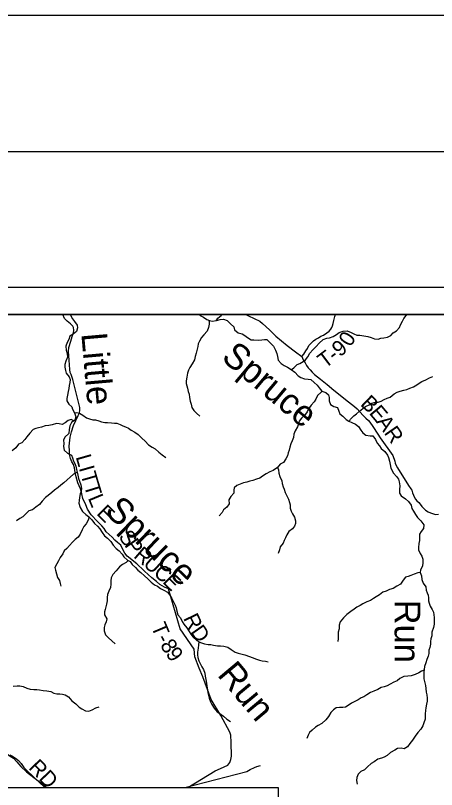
# Model space of a CAD drawing. Extents: x 0 to 34, y 0 to 22.
# Drawn here: x 3.475 to 5.025, y 19.152 to 22 of the extents above; entities that cross this region are included whole.
import ezdxf

# ---------------------------------------------------------------- set-up
doc = ezdxf.new("R2010")
doc.units = 0
for name, color, linetype in [('Default', 7, 'Continuous'), ('GM_X_County_Road', 7, 'Continuous'), ('GM_X_County_Road_Text', 7, 'Continuous'), ('GM_X_Minor_River', 7, 'Continuous'), ('GM_X_Minor_River_Text', 7, 'Continuous'), ('GM_X_Township_Road', 7, 'Continuous'), ('GM_X_Township_Road_Text', 7, 'Continuous'), ('SH_Border', 7, 'Continuous'), ('SH_Cut_Line', 7, 'Continuous'), ('SH_Data', 7, 'Continuous'), ('SH_Text', 7, 'Continuous')]:
    doc.layers.add(name, color=color, linetype=linetype)

msp = doc.modelspace()

# ---------------------------------------------------------------- linework, layer by layer
at = {"layer": 'Default'}
msp.add_lwpolyline([(6.416, 20.9), (2.4845, 20.9)], dxfattribs=at)
at = {"layer": 'GM_X_County_Road'}
msp.add_lwpolyline([(4.3231, 20.9), (4.3324, 20.8951), (4.3741, 20.8748), (4.3839, 20.867), (4.4096, 20.8432), (4.4335, 20.8197), (4.4747, 20.7858), (4.5065, 20.7623), (4.5286, 20.7453), (4.5344, 20.7334), (4.5416, 20.7214), (4.5469, 20.712), (4.5525, 20.7041), (4.5594, 20.6957), (4.567, 20.6873), (4.5759, 20.6795), (4.598, 20.6614), (4.6224, 20.6418), (4.6469, 20.6212), (4.7007, 20.5781), (4.7232, 20.5614), (4.7333, 20.5528), (4.7539, 20.5294), (4.7644, 20.5187), (4.774, 20.5093), (4.7794, 20.5037), (4.7906, 20.4872), (4.8089, 20.4592), (4.8178, 20.4457), (4.8635, 20.3806), (4.8671, 20.3738), (4.8691, 20.3679), (4.8714, 20.36), (4.873, 20.3524), (4.8765, 20.344), (4.8813, 20.3354), (4.9223, 20.2713), (4.9304, 20.2588), (4.9337, 20.253), (4.937, 20.2435), (4.9398, 20.2354), (4.9424, 20.2285), (4.9475, 20.2209), (4.9523, 20.2145), (4.9592, 20.2079), (4.9648, 20.2016), (4.9709, 20.1934), (4.9782, 20.1856), (4.9843, 20.1802), (4.9938, 20.1741), (5.0032, 20.1698), (5.0133, 20.1662), (5.0212, 20.1644), (5.0322, 20.165)], dxfattribs=at)
at = {"layer": 'GM_X_Minor_River'}
for points in [[(3.6775, 20.9), (3.6777, 20.8975), (3.6856, 20.8841), (3.6924, 20.8742), (3.7021, 20.8609), (3.7032, 20.851), (3.7005, 20.8377), (3.6879, 20.8279), (3.6757, 20.8204), (3.6718, 20.8075), (3.6653, 20.7965), (3.6603, 20.7833), (3.6617, 20.7692), (3.6658, 20.7559), (3.6665, 20.7426), (3.6603, 20.7282), (3.6564, 20.7153), (3.6575, 20.7058), (3.6589, 20.6936), (3.6623, 20.6837), (3.6724, 20.6711), (3.6765, 20.6601), (3.6757, 20.6499), (3.6733, 20.6392), (3.6717, 20.6271), (3.6694, 20.6168), (3.6667, 20.6032), (3.6643, 20.5914), (3.6646, 20.5816), (3.6721, 20.5705), (3.6823, 20.5605), (3.6856, 20.551), (3.692, 20.5381), (3.6972, 20.5232), (3.6937, 20.5107), (3.6811, 20.5021), (3.6754, 20.4903), (3.6734, 20.4767), (3.6714, 20.4626), (3.6565, 20.449), (3.6515, 20.4373), (3.6537, 20.4251), (3.6525, 20.4137), (3.6551, 20.4012), (3.6671, 20.3893), (3.6815, 20.3828), (3.6852, 20.3729), (3.6885, 20.3607), (3.6934, 20.3512), (3.6975, 20.3417), (3.6997, 20.3295), (3.7027, 20.3196), (3.7053, 20.3089), (3.7075, 20.2968), (3.7112, 20.2869), (3.716, 20.2728), (3.7182, 20.2595), (3.7166, 20.25), (3.7131, 20.2401), (3.7104, 20.2261), (3.7092, 20.2155), (3.7091, 20.206), (3.7132, 20.1892), (3.7214, 20.1748), (3.7342, 20.1637), (3.7441, 20.1571), (3.7565, 20.1441), (3.7666, 20.1312), (3.7776, 20.1212), (3.7855, 20.1113), (3.7941, 20.0979), (3.8035, 20.085), (3.8141, 20.0769), (3.8265, 20.0643), (3.8344, 20.0517), (3.846, 20.0395)], [(4.1871, 20.8783), (4.188, 20.8737), (4.1883, 20.8642), (4.1859, 20.8521), (4.1805, 20.8388), (4.1691, 20.8256), (4.1595, 20.8154), (4.1522, 20.8021), (4.148, 20.7919), (4.146, 20.7817), (4.1429, 20.7673), (4.1402, 20.7574), (4.1371, 20.7453), (4.1336, 20.7331), (4.1251, 20.718), (4.1167, 20.7044), (4.1121, 20.6945), (4.1086, 20.6843), (4.1055, 20.6695), (4.1038, 20.6562), (4.1038, 20.6463), (4.1086, 20.6285), (4.1112, 20.6167), (4.1141, 20.6064), (4.1156, 20.595), (4.1185, 20.5809), (4.1222, 20.5703), (4.1248, 20.5573), (4.1319, 20.5466), (4.141, 20.5371), (4.1534, 20.5264)], [(4.1514, 20.9), (4.1548, 20.8959), (4.1676, 20.8902)], [(4.1676, 20.8902), (4.1793, 20.881), (4.1895, 20.8775), (4.1997, 20.8748), (4.2149, 20.8773), (4.2282, 20.8818), (4.2415, 20.8825), (4.2547, 20.8775), (4.2672, 20.8652), (4.2785, 20.8549), (4.2814, 20.8439), (4.2954, 20.8328), (4.3094, 20.8281), (4.3192, 20.822), (4.3294, 20.8154), (4.3426, 20.807), (4.3529, 20.8062), (4.3684, 20.8057), (4.3817, 20.8071), (4.3912, 20.8082), (4.4006, 20.8074), (4.4131, 20.7955), (4.4244, 20.7837), (4.4322, 20.7692), (4.4367, 20.7559), (4.4393, 20.7448), (4.4418, 20.7323), (4.4535, 20.7201), (4.4641, 20.7128), (4.4766, 20.7062), (4.4898, 20.6978), (4.503, 20.6875), (4.5154, 20.6737), (4.5252, 20.6683), (4.5392, 20.6633), (4.5525, 20.6621), (4.562, 20.6613), (4.5752, 20.6502), (4.5857, 20.6395), (4.5936, 20.6299), (4.6034, 20.6177), (4.6174, 20.6127), (4.6279, 20.6046), (4.6294, 20.5947), (4.6293, 20.5826), (4.6353, 20.5689), (4.647, 20.5616), (4.6606, 20.5581), (4.6654, 20.544), (4.6692, 20.5345), (4.6797, 20.5253), (4.6922, 20.5138), (4.7024, 20.508), (4.713, 20.5027), (4.7266, 20.4965), (4.7375, 20.4877), (4.7469, 20.4739), (4.7533, 20.4644), (4.7646, 20.4556), (4.7801, 20.4536), (4.7911, 20.4535), (4.8009, 20.4398), (4.8069, 20.4268), (4.8148, 20.4162), (4.8211, 20.4066), (4.8343, 20.3955), (4.8445, 20.3829), (4.8478, 20.3734), (4.8523, 20.3608), (4.8537, 20.3483), (4.8571, 20.335), (4.8668, 20.3159), (4.8777, 20.3041), (4.8849, 20.2942), (4.8878, 20.2843), (4.8896, 20.2691), (4.8888, 20.2554), (4.8883, 20.2429), (4.8947, 20.2326), (4.9109, 20.2222), (4.9222, 20.2115), (4.9312, 20.1985), (4.9342, 20.1856), (4.9398, 20.1757), (4.9473, 20.1635), (4.9552, 20.1528), (4.9673, 20.1413), (4.9781, 20.1257), (4.9773, 20.1128), (4.9689, 20.1018), (4.962, 20.092), (4.9627, 20.0787), (4.9626, 20.0688), (4.9599, 20.057), (4.959, 20.043), (4.9589, 20.0335), (4.9649, 20.0205), (4.9709, 20.0102), (4.9739, 20), (4.9746, 19.987), (4.9737, 19.9738)], [(4.2135, 20.8771), (4.2199, 20.8868), (4.2329, 20.8962), (4.236, 20.9)], [(4.4909, 20.6969), (4.4997, 20.7034), (4.5119, 20.7155), (4.5222, 20.72), (4.5336, 20.7268), (4.5431, 20.7332), (4.5511, 20.7441), (4.5592, 20.7581), (4.5691, 20.7695), (4.5821, 20.7823), (4.5928, 20.7944), (4.6073, 20.8083), (4.6206, 20.8132), (4.6316, 20.8135), (4.6445, 20.8191), (4.6571, 20.8259), (4.6666, 20.8338), (4.6811, 20.8383), (4.6955, 20.8401), (4.7102, 20.8331), (4.7205, 20.8293), (4.7322, 20.8239), (4.7424, 20.8238), (4.7572, 20.8211), (4.7723, 20.8191), (4.7844, 20.8152), (4.7965, 20.8109), (4.8102, 20.8093), (4.8201, 20.813), (4.8307, 20.8141), (4.844, 20.8163), (4.8569, 20.8227), (4.8653, 20.8325), (4.8771, 20.8393), (4.8886, 20.8514), (4.8928, 20.862), (4.8994, 20.8752), (4.9051, 20.8851), (4.9128, 20.8956), (4.9151, 20.9)], [(4.7042, 20.5071), (4.7077, 20.5145), (4.7207, 20.5269), (4.7302, 20.5348), (4.7409, 20.5443), (4.7531, 20.5544), (4.7638, 20.5616), (4.7771, 20.568), (4.7874, 20.574), (4.8007, 20.5777), (4.8101, 20.5772), (4.8208, 20.581), (4.8326, 20.5877), (4.8429, 20.5922), (4.8546, 20.5963), (4.8695, 20.6076), (4.8805, 20.6136), (4.8916, 20.6174), (4.9049, 20.6214), (4.9159, 20.6244), (4.9269, 20.6285), (4.9398, 20.6341), (4.952, 20.6413), (4.9615, 20.6477), (4.9711, 20.6537), (4.9855, 20.6597), (4.9996, 20.6664), (5.011, 20.6713)], [(4.6041, 20.6174), (4.5995, 20.6124), (4.5873, 20.6015), (4.5804, 20.5882), (4.5747, 20.578), (4.5636, 20.5663), (4.5536, 20.5531), (4.5494, 20.5413), (4.5395, 20.5285), (4.5284, 20.5183), (4.5196, 20.5073), (4.5165, 20.4978), (4.5134, 20.4868), (4.5042, 20.4721), (4.4996, 20.4596), (4.498, 20.4478), (4.4933, 20.4349), (4.4883, 20.4243), (4.4848, 20.4118), (4.4829, 20.4012), (4.4786, 20.3906), (4.4759, 20.3803), (4.4705, 20.3682), (4.4621, 20.3557), (4.4499, 20.3494), (4.4392, 20.3369), (4.4243, 20.326), (4.4118, 20.3215), (4.3985, 20.314), (4.3844, 20.3046), (4.3741, 20.2971), (4.3619, 20.2941), (4.3483, 20.2892), (4.3384, 20.2863), (4.3274, 20.2833), (4.3144, 20.28), (4.3019, 20.2755), (4.2905, 20.2702), (4.2802, 20.2627), (4.2794, 20.2532), (4.2785, 20.2426), (4.2678, 20.2305), (4.2609, 20.2184), (4.2612, 20.2036), (4.2536, 20.1907), (4.2406, 20.1813), (4.2356, 20.1715), (4.2249, 20.1594)], [(3.6921, 20.5379), (3.7, 20.5388), (3.7106, 20.5368), (3.7238, 20.5291), (3.737, 20.5196), (3.748, 20.5164), (3.7605, 20.5126), (3.7703, 20.5117), (3.7817, 20.5083), (3.7915, 20.5055), (3.8044, 20.5028), (3.8146, 20.5027), (3.8286, 20.5007), (3.8393, 20.4999), (3.8487, 20.4995), (3.8605, 20.4956), (3.8703, 20.4906), (3.8805, 20.4871), (3.8907, 20.4821), (3.9017, 20.4748), (3.9141, 20.4675), (3.927, 20.4579), (3.9398, 20.4453), (3.953, 20.4338), (3.965, 20.4201), (3.979, 20.4113), (3.9892, 20.4055), (4.0027, 20.3929), (4.0152, 20.3841), (4.0288, 20.3737)], [(3.6901, 20.5082), (3.6805, 20.5131), (3.6687, 20.5101), (3.6588, 20.5018), (3.647, 20.4954), (3.6367, 20.497), (3.6258, 20.4982), (3.6098, 20.4942), (3.5977, 20.492), (3.584, 20.4898), (3.5711, 20.4857), (3.5601, 20.4823), (3.5502, 20.4809), (3.5399, 20.4764), (3.5285, 20.4635), (3.5166, 20.4503), (3.5097, 20.4401), (3.499, 20.428), (3.4868, 20.4224), (3.4765, 20.4092), (3.4634, 20.3985)], [(4.4395, 20.3373), (4.4429, 20.3278), (4.4447, 20.316), (4.4485, 20.3042), (4.4552, 20.2878), (4.4574, 20.2783), (4.4611, 20.2661), (4.4637, 20.2566), (4.4682, 20.2444), (4.4749, 20.2303), (4.4801, 20.22), (4.4842, 20.2086), (4.4864, 20.1991), (4.4867, 20.1873), (4.4901, 20.1767), (4.4946, 20.1664), (4.5024, 20.1538), (4.5061, 20.1409), (4.5053, 20.1314), (4.5018, 20.1215), (4.4949, 20.1109), (4.4812, 20.1019), (4.4739, 20.0894), (4.4697, 20.0776), (4.4643, 20.0678), (4.4608, 20.058), (4.4494, 20.0447), (4.4474, 20.0341), (4.4416, 20.0209)], [(3.7024, 20.3205), (3.6985, 20.317), (3.689, 20.3128), (3.6772, 20.3015), (3.6653, 20.291), (3.6527, 20.28), (3.6421, 20.2721), (3.6322, 20.2635), (3.6192, 20.2533), (3.6097, 20.2454), (3.5959, 20.2337), (3.5864, 20.2269), (3.5738, 20.2133), (3.5639, 20.2008), (3.5505, 20.1907), (3.5379, 20.1816), (3.5246, 20.1772), (3.512, 20.1647), (3.5021, 20.156), (3.4918, 20.1489), (3.4785, 20.1402)], [(3.7461, 20.155), (3.7432, 20.1427), (3.7352, 20.1298), (3.7275, 20.12), (3.7206, 20.1071), (3.7133, 20.092), (3.7064, 20.0806), (3.6953, 20.072), (3.685, 20.0618), (3.674, 20.0497), (3.6644, 20.0391), (3.6549, 20.0305), (3.6491, 20.0195), (3.6395, 20.0059), (3.6338, 19.993), (3.628, 19.9831), (3.6203, 19.9695), (3.6222, 19.9596), (3.6303, 19.9322), (3.6378, 19.9208), (3.64, 19.9101), (3.6419, 19.9006)], [(3.846, 20.0395), (3.857, 20.0299), (3.8679, 20.0185), (3.8743, 20.0078), (3.8875, 19.9963), (3.8973, 19.9913), (3.9044, 19.9802), (3.9165, 19.9695), (3.9259, 19.9588), (3.9368, 19.95), (3.9504, 19.9382), (3.9621, 19.9278), (3.9753, 19.9148), (3.9873, 19.9056), (3.9976, 19.9003), (4.0092, 19.8914), (4.0217, 19.8853), (4.0346, 19.878), (4.0432, 19.8669), (4.0503, 19.8547), (4.0578, 19.8402), (4.0634, 19.8307), (4.0668, 19.8204), (4.069, 19.8079), (4.0727, 19.7953), (4.0821, 19.7842), (4.0885, 19.7709), (4.0944, 19.7606), (4.1065, 19.7476), (4.1144, 19.7331), (4.1207, 19.7232), (4.1298, 19.7129), (4.1433, 19.7003), (4.1562, 19.693), (4.1713, 19.6876), (4.185, 19.6863), (4.1944, 19.6855), (4.2047, 19.6832), (4.2187, 19.6812), (4.2301, 19.6811), (4.2426, 19.6795), (4.2566, 19.6756), (4.269, 19.6679), (4.2834, 19.658), (4.2951, 19.6537), (4.3053, 19.6514), (4.3193, 19.6475), (4.3367, 19.6413), (4.3466, 19.6374), (4.3624, 19.6313), (4.373, 19.6281), (4.3829, 19.6254), (4.3958, 19.6238), (4.4056, 19.6222)], [(3.89, 19.995), (3.8825, 19.9876), (3.8695, 19.9805), (3.8577, 19.971), (3.8462, 19.9567), (3.8336, 19.9435), (3.8271, 19.9314), (3.8263, 19.9203), (3.8262, 19.9082), (3.8246, 19.8953), (3.8188, 19.8824), (3.8138, 19.8695), (3.8126, 19.8585), (3.8133, 19.8467), (3.8098, 19.8338), (3.8078, 19.8244), (3.8059, 19.8149), (3.8035, 19.8054), (3.8031, 19.7944), (3.8117, 19.7799), (3.8097, 19.7696), (3.8047, 19.7583), (3.802, 19.748), (3.8012, 19.7359), (3.8068, 19.7218), (3.8173, 19.71), (3.8305, 19.6996), (3.8426, 19.6882)], [(4.9737, 19.9738), (4.966, 19.9609), (4.9652, 19.951), (4.9693, 19.9381), (4.9707, 19.9252), (4.9756, 19.9111), (4.985, 19.8981), (4.9864, 19.8859), (4.9901, 19.8764), (4.9946, 19.8669), (4.9957, 19.857), (4.9956, 19.8467), (4.9975, 19.8372), (5.0016, 19.8262), (5.0083, 19.8144), (5.0139, 19.8045), (5.0154, 19.795), (5.0164, 19.7847), (5.0163, 19.7604), (5.0143, 19.7486), (5.0081, 19.7316), (5.0073, 19.7179), (5.0038, 19.7069), (5.003, 19.6967), (5.0029, 19.6868), (4.9998, 19.6746), (4.9967, 19.6652), (4.9966, 19.6526), (4.9943, 19.6428), (4.9889, 19.6303), (4.9854, 19.6178), (4.9804, 19.6053), (4.9791, 19.5943), (4.9783, 19.5836), (4.9779, 19.5738), (4.9782, 19.5597), (4.9807, 19.5494), (4.9848, 19.535), (4.9851, 19.5239), (4.9862, 19.5103), (4.9888, 19.5007), (4.9909, 19.4878), (4.9909, 19.4768), (4.9885, 19.4666), (4.985, 19.4525), (4.9838, 19.4427), (4.983, 19.4301), (4.9837, 19.4206), (4.9836, 19.4108), (4.9786, 19.3971), (4.974, 19.3865), (4.9674, 19.3736), (4.9564, 19.3616), (4.946, 19.3483), (4.9361, 19.3343), (4.9265, 19.3211), (4.9185, 19.3086), (4.9055, 19.3022), (4.8945, 19.3046), (4.8813, 19.3032), (4.8714, 19.2975), (4.8561, 19.2881), (4.8432, 19.2776), (4.8325, 19.2708), (4.8223, 19.2678), (4.8093, 19.2634), (4.7956, 19.2539), (4.7838, 19.2476), (4.7712, 19.2355), (4.7594, 19.2249), (4.7465, 19.2182), (4.7369, 19.2091), (4.7319, 19.1962), (4.7307, 19.1856), (4.7329, 19.1719)], [(4.9652, 19.951), (4.9557, 19.9496), (4.9432, 19.9443), (4.9299, 19.9391), (4.9204, 19.9361), (4.9105, 19.9331), (4.9017, 19.9222), (4.8921, 19.9082), (4.8792, 19.8999), (4.8659, 19.892), (4.8518, 19.8876), (4.8396, 19.8816), (4.8278, 19.8778), (4.8149, 19.868), (4.8031, 19.8605), (4.7924, 19.8545), (4.7814, 19.847), (4.7681, 19.8429), (4.754, 19.835), (4.7437, 19.8294), (4.7312, 19.8234), (4.7213, 19.8162), (4.7091, 19.8076), (4.6946, 19.7966), (4.6831, 19.7842), (4.6705, 19.7694), (4.6663, 19.7569), (4.6662, 19.7436), (4.663, 19.7311), (4.6626, 19.7213), (4.6629, 19.7083), (4.6621, 19.6962)], [(4.1507, 19.6961), (4.1493, 19.6843), (4.1477, 19.6718), (4.1453, 19.6581), (4.1453, 19.6478), (4.1467, 19.6383), (4.1501, 19.6258), (4.156, 19.6132), (4.1609, 19.6033), (4.1669, 19.5934), (4.1725, 19.5797), (4.1739, 19.5687), (4.1754, 19.5565), (4.1783, 19.5432), (4.1798, 19.5333), (4.1816, 19.5192), (4.183, 19.5082), (4.1856, 19.4983), (4.1886, 19.4888), (4.193, 19.4743), (4.1979, 19.4648), (4.2065, 19.4514), (4.2178, 19.4385), (4.228, 19.4323), (4.2412, 19.4216), (4.2533, 19.4109), (4.2661, 19.4024)], [(4.9789, 19.5908), (4.9692, 19.5875), (4.9597, 19.5811), (4.9464, 19.5755), (4.932, 19.5702), (4.9187, 19.5696), (4.9043, 19.5678), (4.8898, 19.5606), (4.8799, 19.5523), (4.8673, 19.5475), (4.854, 19.54), (4.843, 19.5336), (4.8316, 19.5299), (4.8217, 19.5273), (4.8084, 19.5198), (4.7947, 19.5145), (4.7814, 19.5089), (4.7688, 19.5003), (4.7574, 19.4935), (4.7479, 19.489), (4.7365, 19.4826), (4.7247, 19.4762), (4.7117, 19.4699), (4.6999, 19.4616), (4.6896, 19.4552), (4.6798, 19.4534), (4.6673, 19.4534), (4.6555, 19.4527), (4.6456, 19.4452), (4.6357, 19.4358), (4.6269, 19.4214), (4.6177, 19.4085), (4.6028, 19.3946), (4.5891, 19.3878), (4.5796, 19.3818), (4.5674, 19.3701), (4.5578, 19.3618), (4.5528, 19.3516), (4.5471, 19.3399)], [(3.4672, 19.5318), (3.4813, 19.5336), (3.4908, 19.5335), (3.5033, 19.5308), (3.5173, 19.5254), (3.5297, 19.5215), (3.543, 19.5199), (3.554, 19.5198), (3.5635, 19.519), (3.5767, 19.5163), (3.5908, 19.5154), (3.6051, 19.5127), (3.6165, 19.5069), (3.6278, 19.5038), (3.6385, 19.5045), (3.6479, 19.5033), (3.6582, 19.5005), (3.6702, 19.4929), (3.6823, 19.4787), (3.697, 19.4676), (3.7098, 19.4546), (3.72, 19.4485), (3.7328, 19.4416), (3.7453, 19.44), (3.7579, 19.4456), (3.7705, 19.4531), (3.7834, 19.4568)], [(3.4542, 19.2796), (3.4621, 19.2766), (3.4753, 19.2677), (3.4859, 19.2593), (3.4964, 19.2475), (3.5062, 19.2337), (3.5186, 19.2207), (3.5835, 19.1594)], [(4.099, 19.1594), (4.3263, 19.2186), (4.3393, 19.2261), (4.3545, 19.2332), (4.364, 19.237), (4.3765, 19.2407)]]:
    msp.add_lwpolyline(points, dxfattribs=at)
at = {"layer": 'GM_X_Township_Road'}
for points in [[(3.9502, 19.9557), (3.9472, 19.9584), (3.9215, 19.9829), (3.8869, 20.0108), (3.8775, 20.0218), (3.8681, 20.0403), (3.8628, 20.0513), (3.8513, 20.0607), (3.8404, 20.0698), (3.8307, 20.0805), (3.8198, 20.0907), (3.8089, 20.1006), (3.8012, 20.1126), (3.7936, 20.1222), (3.7773, 20.1383), (3.7542, 20.1624), (3.7407, 20.1838), (3.7338, 20.1995), (3.7234, 20.2227), (3.7196, 20.2395), (3.7142, 20.2583), (3.705, 20.2809), (3.6987, 20.302), (3.6954, 20.3186), (3.6926, 20.3351), (3.6886, 20.3481), (3.6832, 20.3582), (3.6781, 20.3704), (3.6746, 20.3844), (3.6736, 20.4), (3.6728, 20.416), (3.6751, 20.4371), (3.6768, 20.4485), (3.6814, 20.4686), (3.6893, 20.492), (3.7066, 20.5284), (3.7104, 20.5382), (3.7127, 20.5477), (3.7125, 20.5571), (3.6868, 20.6606), (3.6799, 20.6789), (3.6769, 20.6868), (3.6748, 20.6973), (3.6728, 20.7321), (3.6705, 20.7639), (3.6723, 20.7786), (3.6789, 20.8013), (3.6837, 20.8191), (3.6883, 20.8328), (3.6901, 20.8427), (3.6893, 20.8516), (3.6865, 20.8573), (3.6784, 20.8649), (3.6659, 20.8748), (3.6552, 20.8852), (3.6491, 20.8994), (3.6491, 20.9)], [(4.5286, 20.7453), (4.5363, 20.7535), (4.5441, 20.7659), (4.5495, 20.7746), (4.5555, 20.7856), (4.564, 20.7949), (4.5724, 20.8024), (4.5813, 20.8087), (4.5902, 20.814), (4.5991, 20.8197), (4.6087, 20.8242), (4.6218, 20.8322), (4.63, 20.8387), (4.6356, 20.8455), (4.6391, 20.8518), (4.6423, 20.8582), (4.6448, 20.867), (4.6469, 20.8776), (4.6511, 20.8923), (4.6531, 20.9)], [(4.1518, 19.5989), (4.1356, 19.6407), (4.1333, 19.6681), (4.0814, 19.7434), (4.038, 19.8905), (4.0233, 19.8961), (4.0065, 19.9068), (3.9938, 19.917), (3.9772, 19.9307), (3.9502, 19.9557)], [(4.1092, 19.1594), (4.21, 19.2208), (4.2295, 19.2289), (4.2573, 19.242), (4.264, 19.2519), (4.2681, 19.2632), (4.2703, 19.2746), (4.2687, 19.3252), (4.2675, 19.3518), (4.2638, 19.3627), (4.2312, 19.4247), (4.1953, 19.4835), (4.1643, 19.5667), (4.1518, 19.5989)], [(3.108, 19.5852), (3.1171, 19.5808), (3.1313, 19.5736), (3.1822, 19.5459), (3.1977, 19.5378), (3.2094, 19.5302), (3.2239, 19.5185), (3.2376, 19.5035), (3.2529, 19.4834), (3.2763, 19.4498), (3.2941, 19.4277), (3.3246, 19.3933), (3.3684, 19.3473), (3.4093, 19.3132), (3.433, 19.2921), (3.4559, 19.2746), (3.4686, 19.2672), (3.4808, 19.2542), (3.495, 19.2374), (3.5161, 19.2168), (3.5906, 19.1594)]]:
    msp.add_lwpolyline(points, dxfattribs=at)
at = {"layer": 'SH_Border'}
msp.add_lwpolyline([(1.5, 21.5), (33.5, 21.5), (33.5, 0.5), (1.5, 0.5)], close=True, dxfattribs=at)
at = {"layer": 'SH_Cut_Line'}
for points in [[(0, 0), (34, 0), (34, 22), (0, 22)], [(2.4352, 14.1), (8.9, 14.1), (8.9, 20.9), (2.4845, 20.9), (2.4809, 20.6393), (2.4757, 20.2566), (2.4573, 18.9074), (2.4581, 18.1825), (2.4581, 18.1772), (2.4586, 17.7785), (2.4545, 17.2795), (2.4313, 15.0183), (2.4372, 14.2719)]]:
    msp.add_lwpolyline(points, close=True, dxfattribs=at)
at = {"layer": 'SH_Data'}
for p, q in [((2, 21), (9, 21)), ((2.1, 20.9), (8.9, 20.9))]:
    msp.add_line(p, q, dxfattribs=at)
at = {"layer": 'SH_Text'}
msp.add_lwpolyline([(2.9469, 19.1594), (4.4427, 19.1594), (4.4427, 18.673), (2.9469, 18.673)], close=True, dxfattribs=at)

# ---------------------------------------------------------------- texts
at = {"layer": 'GM_X_County_Road_Text'}
for s, rotation, p in [('B', 316.2586, (4.7417, 20.5678)), ('E', 310.0695, (4.7743, 20.5367)), ('A', 305.3907, (4.8009, 20.5051)), ('R', 304.8376, (4.8298, 20.4645))]:
    msp.add_text(s, height=0.0568, rotation=rotation, dxfattribs=at).set_placement(p)
at = {"layer": 'GM_X_Minor_River_Text'}
for s, rotation, p in [('Little', 275.0003, (3.7175, 20.8297)), ('Spruce', 319.9985, (4.2288, 20.7357)), ('Spruce', 315.9986, (3.7996, 20.1726)), ('Run', 270.0019, (4.8706, 19.8505)), ('Run', 309.9988, (4.2152, 19.5732))]:
    msp.add_text(s, height=0.0947, rotation=rotation, dxfattribs=at).set_placement(p)
at = {"layer": 'GM_X_Township_Road_Text'}
for s, height, rotation, p in [('0', 0.0568, 57.2884, (4.7081, 20.7778)), ('9', 0.0568, 40.6727, (4.6698, 20.7415)), ('T', 0.0568, 37.1296, (4.6145, 20.6991)), ('-', 0.0568, 37.7691, (4.6489, 20.7252)), ('L', 0.0568, 285.8971, (3.6965, 20.3764)), ('I', 0.0568, 285.8974, (3.7082, 20.3355)), ('T', 0.0568, 285.9553, (3.7146, 20.313)), ('T', 0.0568, 286.9651, (3.7266, 20.2711)), ('L', 0.0568, 292.6336, (3.741, 20.2248)), ('E', 0.0568, 315.3115, (3.7708, 20.1657)), ('S', 0.0568, 305.2894, (3.8524, 20.0823)), ('P', 0.0568, 305.0963, (3.8745, 20.0511)), ('R', 0.0568, 319.4642, (3.907, 20.0082)), ('U', 0.0568, 318.2615, (3.9422, 19.9781)), ('C', 0.0568, 318.2417, (3.9795, 19.9448)), ('E', 0.0568, 315.7137, (4.0138, 19.9142)), ('R', 0.0568, 295.7953, (4.0918, 19.7828)), ('T', 0.0568, 292.8969, (3.9733, 19.7521)), ('D', 0.0568, 304.9326, (4.117, 19.7324)), ('-', 0.0568, 297.7915, (3.9921, 19.7082)), ('8', 0.0568, 302.6861, (4.0057, 19.683)), ('9', 0.0568, 305.1334, (4.0261, 19.6513)), ('RD', 0.05682, 313.6193, (3.5205, 19.2306))]:
    msp.add_text(s, height=height, rotation=rotation, dxfattribs=at).set_placement(p)

doc.saveas('drawing.dxf')
